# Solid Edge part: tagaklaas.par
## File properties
Author: Türk
Template: iso part.par
Last saved by: Türk
Revision: 10
Application: Solid Edge
Accuracy: 0,990
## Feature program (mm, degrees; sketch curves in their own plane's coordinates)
base feature "unnamed BaseFeature 1"
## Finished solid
Body 1: solid body, 30 faces, 60 edges, 32 vertices.
  Faces by surface: spline 17, offset 5, blend 4, plane 2, swept 2
  Edges by curve: curve on surface 32, intersection 16, spline 10, line 2
Body 2: sheet body, 7 faces, 20 edges, 14 vertices.
  Faces by surface: spline 5, blend 2
  Edges by curve: spline 10, intersection 6, curve on surface 2, line 2
Bounding box of the edges (mm; curved faces can reach further): 1300.000 x 344.984 x 291.110, from (-650, 2175.0159, 546.1726) to (650, 2520, 837.2828).
Planar faces by outward normal: oblique 2
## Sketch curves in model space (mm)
spline (-568.0927, 2520, 550) -> (-611.335, 2477.3671, 550) -> (-638.9655, 2411.3629, 550)
line (-568.0927, 2520, 550) -> (568.0927, 2520, 550)
line (595.9573, 2219.8282, 739.1483) -> (650, 2300, 550)
ellipse centre (355.5763, 2248.9386, 670.4684) radii 271.5282, 250 from (572.0859, 2195.9592, 795.4621) through (585.7503, 2207.5831, 768.038) to (595.9573, 2219.8282, 739.1483)
spline (-572.0859, 2195.9592, 795.4621) -> (-535.056, 2182.7615, 826.5991) -> (-486.3268, 2178.2332, 837.2828)
line (486.3268, 2178.2332, 837.2828) -> (-486.3268, 2178.2332, 837.2828)
spline (486.3268, 2178.2332, 837.2828) -> (535.0186, 2182.754, 826.6169) -> (572.0859, 2195.9592, 795.4621)
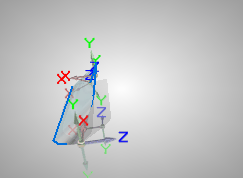
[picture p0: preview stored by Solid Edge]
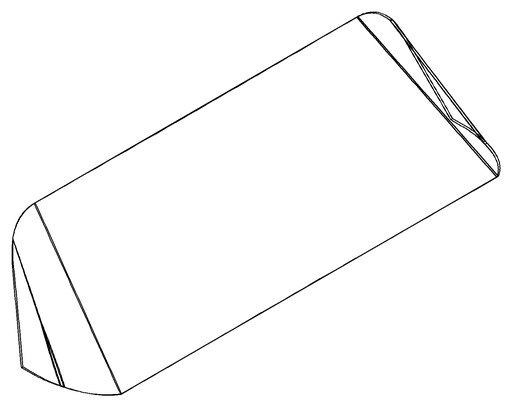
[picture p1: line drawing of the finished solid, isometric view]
